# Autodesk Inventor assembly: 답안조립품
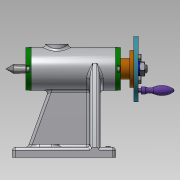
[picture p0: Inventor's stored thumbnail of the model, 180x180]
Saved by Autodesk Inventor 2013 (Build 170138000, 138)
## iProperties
Created: 2019-10
Part Number: 답안조립품
Document SubType Name: Assembly
Designer: hana-cad17
Author: hana-cad17
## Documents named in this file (18)
- C:\Documents and Settings\hana-cad17\바탕 화면\491004V1010\답안조립품.iam
- C:\Documents and Settings\hana-cad17\바탕 화면\491004V1010\본체.ipt
- C:\Documents and Settings\hana-cad17\바탕 화면\491004V1010\슬리브.ipt
- C:\Documents and Settings\hana-cad17\바탕 화면\491004V1010\중공축.ipt
- C:\Documents and Settings\hana-cad17\바탕 화면\491004V1010\센터홀더.ipt
- C:\Documents and Settings\hana-cad17\바탕 화면\491004V1010\멈춤나사 M3.ipt
- C:\Documents and Settings\hana-cad17\바탕 화면\491004V1010\센터.ipt
- C:\Documents and Settings\hana-cad17\바탕 화면\491004V1010\나사.ipt
- C:\Documents and Settings\hana-cad17\바탕 화면\491004V1010\커버.ipt
- C:\Documents and Settings\hana-cad17\바탕 화면\491004V1010\부시.ipt
- C:\Documents and Settings\hana-cad17\바탕 화면\491004V1010\나사축.ipt
- C:\Documents and Settings\hana-cad17\바탕 화면\491004V1010\키 4 x 4 x 10.ipt
- C:\Documents and Settings\hana-cad17\바탕 화면\491004V1010\플랜지.ipt
- C:\Documents and Settings\hana-cad17\바탕 화면\491004V1010\돌림판.ipt
- C:\Documents and Settings\hana-cad17\바탕 화면\491004V1010\와셔.ipt
- C:\Documents and Settings\hana-cad17\바탕 화면\491004V1010\너트 M8.ipt
- C:\Documents and Settings\hana-cad17\바탕 화면\491004V1010\핸들.ipt
- C:\Documents and Settings\hana-cad17\바탕 화면\491004V1010\볼트 M3.ipt
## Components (2 placed, 2 different names)
1. 플랜지:1 — 각도:2
2. 핸들:1
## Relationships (1: Angle 1)
- 각도:2 [Angle]: 플랜지:1
